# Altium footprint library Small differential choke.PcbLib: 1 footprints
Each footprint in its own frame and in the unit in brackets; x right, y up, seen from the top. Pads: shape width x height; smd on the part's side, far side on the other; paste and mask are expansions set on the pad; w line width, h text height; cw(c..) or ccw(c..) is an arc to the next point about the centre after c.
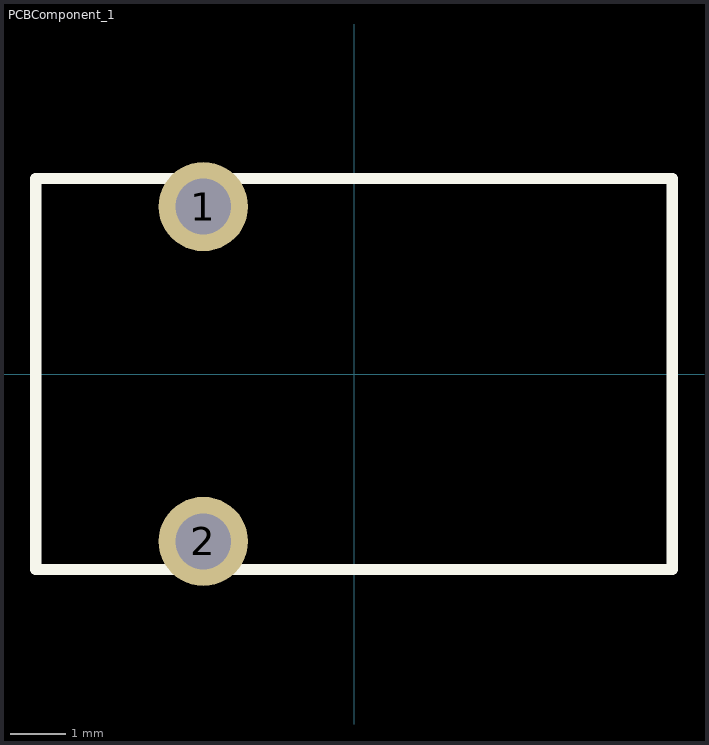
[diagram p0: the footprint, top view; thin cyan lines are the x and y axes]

## PCBComponent_1 [mm]
pads (2):
  round 1.6 hole 1: 1(-2.7,3) 2(-2.7,-3)
Top Overlay:
  lines w0.2: -5.7,-3.5 5.7,-3.5 5.7,3.5 -5.7,3.5 -5.7,-3.5
M5 Assembly Top:
  text ".Designator" at -2,-0.7 h1.85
